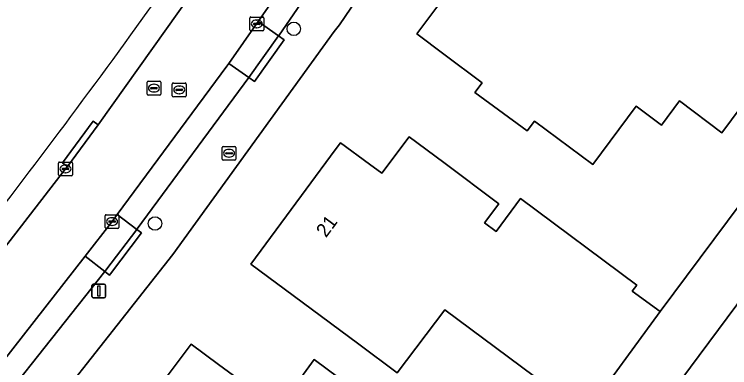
# Model space of a CAD drawing. Extents: x 158835 to 160077, y 386387 to 387778.
# Drawn here: x 159468.8 to 159520.8, y 386635.5 to 386661.1 of the extents above; entities that cross this region are included whole.
import ezdxf

# ---------------------------------------------------------------- set-up
doc = ezdxf.new("R2010")
doc.units = 0
for name, color, linetype in [('IMGEO_Boom', 7, 'Continuous'), ('IMGEO_Brandkraan', 7, 'Continuous'), ('IMGEO_Erf', 7, 'Continuous'), ('IMGEO_Grasland_agrarisch', 7, 'Continuous'), ('IMGEO_Groenvoorziening', 7, 'Continuous'), ('IMGEO_Kolk', 7, 'Continuous'), ('IMGEO_Lichtmast', 7, 'Continuous'), ('IMGEO_Pand', 7, 'Continuous'), ('IMGEO_Pand_nummerreeks', 7, 'Continuous'), ('IMGEO_Parkeervlak_open', 7, 'Continuous'), ('IMGEO_Rijbaan_lokaal_gesloten', 7, 'Continuous'), ('IMGEO_Rioolput', 7, 'Continuous'), ('IMGEO_Voetpad_open', 7, 'Continuous')]:
    doc.layers.add(name, color=color, linetype=linetype)

msp = doc.modelspace()

# ---------------------------------------------------------------- linework, layer by layer
at = {"layer": 'IMGEO_Boom'}
for centre in [(159489.093, 386660.084), (159479.003, 386645.952)]:
    msp.add_circle(centre, 0.489, dxfattribs=at)
at = {"layer": 'IMGEO_Brandkraan'}
for p, q in [((159483.884, 386650.623), (159483.884, 386651.475)), ((159483.959, 386651.549), (159484.811, 386651.549)), ((159484.372, 386651.329), (159484.397, 386651.329)), ((159484.885, 386651.475), (159484.885, 386650.623)), ((159484.143, 386651.043), (159484.143, 386651.055)), ((159484.581, 386651.006), (159484.183, 386651.006)), ((159484.186, 386651.092), (159484.584, 386651.092)), ((159484.395, 386650.769), (159484.37, 386650.769)), ((159484.627, 386651.055), (159484.627, 386651.043)), ((159484.811, 386650.549), (159483.959, 386650.549))]:
    msp.add_line(p, q, dxfattribs=at)
for points in [[(159483.884, 386650.623), (159483.884, 386651.475)], [(159483.959, 386651.549), (159484.811, 386651.549)], [(159484.885, 386651.475), (159484.885, 386650.623)], [(159484.811, 386650.549), (159483.959, 386650.549)]]:
    msp.add_lwpolyline(points, dxfattribs=at)
for centre, radius, start, end in [((159483.961, 386651.473), 0.0765, 91.552, 178.448), ((159483.961, 386651.473), 0.0765, 91.552, 178.448), ((159484.809, 386651.473), 0.0765, 1.552, 88.448), ((159484.809, 386651.473), 0.0765, 1.552, 88.448), ((159483.961, 386650.625), 0.0765, 181.552, 268.448), ((159483.961, 386650.625), 0.0765, 181.552, 268.448), ((159484.183, 386651.052), 0.0403, 85.8775, 175.7526), ((159484.18, 386651.042), 0.0366, 178.938, 274.7102), ((159484.584, 386651.049), 0.043, 264.8664, 352.4533), ((159484.588, 386651.054), 0.0386, 1.7309, 96.639), ((159484.809, 386650.625), 0.0765, 271.552, 358.448), ((159484.809, 386650.625), 0.0765, 271.552, 358.448)]:
    msp.add_arc(centre, radius, start, end, dxfattribs=at)
for centre, major_axis, ratio, start_param, end_param in [((159484.371, 386651.049), (-0.387, 0.002), 0.722429, 4.712389, 7.853982), ((159484.396, 386651.049), (-0.39, 0.002), 0.717154, 1.570796, 4.712389)]:
    msp.add_ellipse(centre, major_axis=major_axis, ratio=ratio, start_param=start_param, end_param=end_param, dxfattribs=at)
at = {"layer": 'IMGEO_Erf'}
for points in [[(159523.936, 386720.207), (159523.989, 386717.606), (159523.81, 386715.012), (159523.4, 386712.444), (159522.762, 386709.923), (159521.901, 386707.468), (159520.825, 386705.101), (159506.854, 386682.053), (159500.252, 386671.907), (159500, 386671.529), (159492.426, 386660.371), (159492.025, 386659.896), (159480.297, 386643.692), (159466.865, 386626.712)], [(159523.113, 386656.41), (159520.227, 386652.544), (159517.144, 386654.846), (159515.832, 386653.089), (159513.995, 386654.46), (159510.835, 386650.227), (159506.602, 386653.387), (159506.065, 386652.668), (159502.272, 386655.46), (159502.798, 386656.164), (159500, 386658.253), (159498.048, 386659.711), (159500, 386662.363)], [(159510.292, 386632.116), (159500.067, 386639.683), (159496.612, 386635.111), (159493.813, 386637.183), (159489.698, 386640.229), (159485.96, 386642.995), (159489.992, 386648.443), (159492.11, 386651.289), (159492.501, 386651.811), (159494.608, 386650.269), (159495.495, 386649.612), (159497.478, 386652.247), (159500, 386650.371), (159504.011, 386647.387), (159502.97, 386645.987), (159503.805, 386645.366), (159505.572, 386647.754), (159514.036, 386641.48), (159513.714, 386641.046), (159515.731, 386639.551), (159526.452, 386653.918)], [(159478.952, 386633.598), (159481.628, 386637.182), (159483.619, 386635.721), (159487.975, 386632.524), (159490.58, 386636.073), (159500, 386629.075)]]:
    msp.add_lwpolyline(points, dxfattribs=at)
for centre, radius, start, end in [((159034.245, 386981.09), 547.337, 323.34107, 325.81472), ((158997.141, 387009.134), 593.846, 321.080124, 323.307898)]:
    msp.add_arc(centre, radius, start, end, dxfattribs=at)
at = {"layer": 'IMGEO_Grasland_agrarisch'}
msp.add_lwpolyline([(159627.547, 386754.968), (159626.26, 386754.636), (159608.282, 386750), (159603.124, 386748.673), (159599.84, 386747.828), (159600.163, 386746.978), (159599.236, 386744.729), (159497.576, 386608.169), (159496.856, 386607.202), (159474.258, 386576.846)], dxfattribs=at)
at = {"layer": 'IMGEO_Groenvoorziening'}
msp.add_lwpolyline([(159599.236, 386744.729), (159600.163, 386746.978), (159599.84, 386747.828), (159595.413, 386746.689), (159591.302, 386741.165), (159576.147, 386720.781), (159563.63, 386703.915), (159558.058, 386696.441), (159540.934, 386673.397), (159533.385, 386663.269), (159529.001, 386657.369), (159526.452, 386653.918), (159515.731, 386639.551), (159510.292, 386632.116), (159505.124, 386625.269), (159502.142, 386621.255), (159495.593, 386611.141), (159497.576, 386608.169)], close=True, dxfattribs=at)
at = {"layer": 'IMGEO_Kolk'}
for p, q in [((159485.905, 386660.016), (159485.905, 386660.868)), ((159485.98, 386660.942), (159486.832, 386660.942)), ((159486.207, 386660.485), (159486.605, 386660.485)), ((159486.393, 386660.722), (159486.418, 386660.722)), ((159486.906, 386660.868), (159486.906, 386660.016)), ((159486.164, 386660.436), (159486.164, 386660.448)), ((159486.602, 386660.399), (159486.204, 386660.399)), ((159486.416, 386660.162), (159486.391, 386660.162)), ((159486.648, 386660.448), (159486.648, 386660.436)), ((159486.832, 386659.942), (159485.98, 386659.942)), ((159471.993, 386649.487), (159471.993, 386650.339)), ((159472.068, 386650.413), (159472.92, 386650.413)), ((159472.481, 386650.193), (159472.506, 386650.193)), ((159472.994, 386650.339), (159472.994, 386649.487)), ((159472.252, 386649.907), (159472.252, 386649.919)), ((159472.69, 386649.87), (159472.292, 386649.87)), ((159472.295, 386649.956), (159472.693, 386649.956)), ((159472.504, 386649.633), (159472.479, 386649.633)), ((159472.736, 386649.919), (159472.736, 386649.907)), ((159472.92, 386649.413), (159472.068, 386649.413)), ((159475.379, 386645.663), (159475.379, 386646.515)), ((159475.454, 386646.589), (159476.306, 386646.589)), ((159476.38, 386646.515), (159476.38, 386645.663)), ((159475.638, 386646.083), (159475.638, 386646.095)), ((159476.076, 386646.046), (159475.678, 386646.046)), ((159475.681, 386646.132), (159476.079, 386646.132)), ((159475.867, 386646.369), (159475.892, 386646.369)), ((159476.122, 386646.095), (159476.122, 386646.083)), ((159476.306, 386645.589), (159475.454, 386645.589)), ((159475.89, 386645.809), (159475.865, 386645.809))]:
    msp.add_line(p, q, dxfattribs=at)
for points in [[(159485.905, 386660.016), (159485.905, 386660.868)], [(159485.98, 386660.942), (159486.832, 386660.942)], [(159486.906, 386660.868), (159486.906, 386660.016)], [(159486.832, 386659.942), (159485.98, 386659.942)], [(159471.993, 386649.487), (159471.993, 386650.339)], [(159472.068, 386650.413), (159472.92, 386650.413)], [(159472.994, 386650.339), (159472.994, 386649.487)], [(159472.92, 386649.413), (159472.068, 386649.413)], [(159475.379, 386645.663), (159475.379, 386646.515)], [(159475.454, 386646.589), (159476.306, 386646.589)], [(159476.38, 386646.515), (159476.38, 386645.663)], [(159476.306, 386645.589), (159475.454, 386645.589)]]:
    msp.add_lwpolyline(points, dxfattribs=at)
for centre, radius, start, end in [((159485.982, 386660.866), 0.0765, 91.552, 178.448), ((159485.982, 386660.866), 0.0765, 91.552, 178.448), ((159486.204, 386660.445), 0.0403, 85.8775, 175.7526), ((159486.609, 386660.447), 0.0386, 1.7309, 96.639), ((159486.83, 386660.866), 0.0765, 1.552, 88.448), ((159486.83, 386660.866), 0.0765, 1.552, 88.448), ((159485.982, 386660.018), 0.0765, 181.552, 268.448), ((159485.982, 386660.018), 0.0765, 181.552, 268.448), ((159486.201, 386660.435), 0.0366, 178.938, 274.7102), ((159486.605, 386660.442), 0.043, 264.8664, 352.4533), ((159486.83, 386660.018), 0.0765, 271.552, 358.448), ((159486.83, 386660.018), 0.0765, 271.552, 358.448), ((159472.07, 386650.337), 0.0765, 91.552, 178.448), ((159472.07, 386650.337), 0.0765, 91.552, 178.448), ((159472.918, 386650.337), 0.0765, 1.552, 88.448), ((159472.918, 386650.337), 0.0765, 1.552, 88.448), ((159472.292, 386649.916), 0.0403, 85.8775, 175.7526), ((159472.289, 386649.906), 0.0366, 178.938, 274.7102), ((159472.693, 386649.913), 0.043, 264.8664, 352.4533), ((159472.697, 386649.918), 0.0386, 1.7309, 96.639), ((159472.07, 386649.489), 0.0765, 181.552, 268.448), ((159472.07, 386649.489), 0.0765, 181.552, 268.448), ((159472.918, 386649.489), 0.0765, 271.552, 358.448), ((159472.918, 386649.489), 0.0765, 271.552, 358.448), ((159475.456, 386646.513), 0.0765, 91.552, 178.448), ((159475.456, 386646.513), 0.0765, 91.552, 178.448), ((159476.304, 386646.513), 0.0765, 1.552, 88.448), ((159476.304, 386646.513), 0.0765, 1.552, 88.448), ((159475.678, 386646.092), 0.0403, 85.8775, 175.7526), ((159475.675, 386646.082), 0.0366, 178.938, 274.7102), ((159476.079, 386646.089), 0.043, 264.8664, 352.4533), ((159476.083, 386646.094), 0.0386, 1.7309, 96.639), ((159475.456, 386645.665), 0.0765, 181.552, 268.448), ((159475.456, 386645.665), 0.0765, 181.552, 268.448), ((159476.304, 386645.665), 0.0765, 271.552, 358.448), ((159476.304, 386645.665), 0.0765, 271.552, 358.448)]:
    msp.add_arc(centre, radius, start, end, dxfattribs=at)
for centre, major_axis, ratio, start_param, end_param in [((159486.392, 386660.442), (-0.387, 0.002), 0.722429, 4.712389, 7.853982), ((159486.417, 386660.442), (-0.39, 0.002), 0.717154, 1.570796, 4.712389), ((159472.48, 386649.913), (-0.387, 0.002), 0.722429, 4.712389, 7.853982), ((159472.505, 386649.913), (-0.39, 0.002), 0.717154, 1.570796, 4.712389), ((159475.866, 386646.089), (-0.387, 0.002), 0.722429, 4.712389, 7.853982), ((159475.891, 386646.089), (-0.39, 0.002), 0.717154, 1.570796, 4.712389)]:
    msp.add_ellipse(centre, major_axis=major_axis, ratio=ratio, start_param=start_param, end_param=end_param, dxfattribs=at)
at = {"layer": 'IMGEO_Lichtmast'}
for p, q in [((159474.417, 386640.653), (159474.417, 386641.453)), ((159474.417, 386641.453), (159474.417, 386640.653)), ((159474.517, 386641.553), (159475.307, 386641.553)), ((159475.307, 386641.553), (159474.517, 386641.553)), ((159475.407, 386641.453), (159475.407, 386640.653)), ((159475.407, 386640.653), (159475.407, 386641.453)), ((159475.307, 386640.553), (159474.517, 386640.553)), ((159474.517, 386640.553), (159475.307, 386640.553))]:
    msp.add_line(p, q, dxfattribs=at)
msp.add_lwpolyline([(159474.837, 386641.428), (159474.987, 386641.428), (159474.987, 386640.678), (159474.837, 386640.678), (159474.837, 386641.428)], dxfattribs=at)
for centre, start, end in [((159474.517, 386641.453), 90, 180), ((159474.517, 386641.453), 90, 180), ((159475.307, 386641.453), 0, 90), ((159475.307, 386641.453), 360, 90), ((159474.517, 386640.653), 180, 270), ((159474.517, 386640.653), 180, 270), ((159475.307, 386640.653), 270, 0), ((159475.307, 386640.653), 270, 0)]:
    msp.add_arc(centre, 0.1, start, end, dxfattribs=at)
at = {"layer": 'IMGEO_Pand'}
msp.add_lwpolyline([(159500, 386662.363), (159498.048, 386659.711), (159500, 386658.253), (159502.798, 386656.164), (159502.272, 386655.46), (159506.065, 386652.668), (159506.602, 386653.387), (159510.835, 386650.227), (159513.995, 386654.46), (159515.832, 386653.089), (159517.144, 386654.846), (159520.227, 386652.544), (159523.113, 386656.41)], dxfattribs=at)
for points in [[(159505.572, 386647.754), (159503.805, 386645.366), (159502.97, 386645.987), (159504.011, 386647.387), (159500, 386650.371), (159497.478, 386652.247), (159495.495, 386649.612), (159494.608, 386650.269), (159492.501, 386651.811), (159492.11, 386651.289), (159489.992, 386648.443), (159485.96, 386642.995), (159489.698, 386640.229), (159493.813, 386637.183), (159496.612, 386635.111), (159500.067, 386639.683), (159510.292, 386632.116), (159515.731, 386639.551), (159513.714, 386641.046), (159514.036, 386641.48)], [(159505.124, 386625.269), (159500, 386629.075), (159490.58, 386636.073), (159487.975, 386632.524), (159483.619, 386635.721), (159481.628, 386637.182), (159478.952, 386633.598), (159478.302, 386634.081), (159475.9, 386630.854), (159476.551, 386630.374), (159473.82, 386626.723), (159486.632, 386617.139), (159489.513, 386621.073), (159485.776, 386623.902), (159488.853, 386627.967), (159488.149, 386628.5), (159489.612, 386630.434), (159500, 386622.824), (159502.142, 386621.255)]]:
    msp.add_lwpolyline(points, close=True, dxfattribs=at)
at = {"layer": 'IMGEO_Parkeervlak_open'}
for points in [[(159497.546, 386673.509), (159495.988, 386674.563), (159488.253, 386663.123), (159486.494, 386660.609), (159487.977, 386659.57), (159488.022, 386659.633), (159494.875, 386669.563)], [(159485.827, 386656.543), (159484.364, 386657.566), (159484.227, 386657.37), (159476.255, 386646.598), (159477.681, 386645.519), (159477.708, 386645.554)], [(159475.346, 386642.471), (159473.919, 386643.589), (159465.699, 386633.096), (159462.673, 386629.428), (159464.074, 386628.284), (159464.152, 386628.38)]]:
    msp.add_lwpolyline(points, close=True, dxfattribs=at)
at = {"layer": 'IMGEO_Rijbaan_lokaal_gesloten'}
for points in [[(159513.878, 386721.278), (159513.869, 386716.038), (159513.796, 386715.241), (159513.584, 386713.955), (159513.258, 386712.692), (159512.821, 386711.465), (159512.275, 386710.281), (159511.626, 386709.15), (159501.61, 386692.371), (159500.806, 386691.095), (159500, 386689.822), (159499.36, 386688.811), (159497.335, 386685.65), (159492.103, 386677.614), (159491.469, 386676.644), (159491.393, 386676.531), (159488.703, 386672.537), (159488.647, 386672.459), (159474.87, 386653.114), (159472.629, 386650.095), (159472.496, 386649.912), (159463.597, 386638.445)], [(159465.699, 386633.096), (159473.919, 386643.589), (159475.879, 386646.09), (159476.255, 386646.598), (159484.227, 386657.37), (159484.364, 386657.566), (159486.494, 386660.609), (159488.253, 386663.123), (159495.988, 386674.563), (159498.178, 386677.802), (159500, 386680.496), (159500.64, 386681.505), (159502.694, 386684.743), (159505.787, 386689.619), (159516.302, 386707.245), (159517.076, 386708.722), (159517.443, 386709.606), (159517.715, 386710.261), (159518.213, 386711.852), (159518.439, 386712.887), (159518.568, 386713.481), (159518.776, 386715.135), (159518.834, 386716.37), (159518.864, 386721.239)]]:
    msp.add_lwpolyline(points, dxfattribs=at)
at = {"layer": 'IMGEO_Rioolput'}
for p, q in [((159478.424, 386655.351), (159478.424, 386656.203)), ((159478.499, 386656.277), (159479.351, 386656.277)), ((159478.683, 386655.771), (159478.683, 386655.783)), ((159478.726, 386655.82), (159479.124, 386655.82)), ((159478.912, 386656.057), (159478.937, 386656.057)), ((159479.167, 386655.783), (159479.167, 386655.771)), ((159479.425, 386656.203), (159479.425, 386655.351)), ((159480.262, 386655.224), (159480.262, 386656.076)), ((159480.337, 386656.15), (159481.189, 386656.15)), ((159480.75, 386655.93), (159480.775, 386655.93)), ((159481.263, 386656.076), (159481.263, 386655.224)), ((159479.351, 386655.277), (159478.499, 386655.277)), ((159479.121, 386655.734), (159478.723, 386655.734)), ((159478.935, 386655.497), (159478.91, 386655.497)), ((159480.521, 386655.644), (159480.521, 386655.656)), ((159480.959, 386655.607), (159480.561, 386655.607)), ((159480.564, 386655.693), (159480.962, 386655.693)), ((159480.773, 386655.37), (159480.748, 386655.37)), ((159481.005, 386655.656), (159481.005, 386655.644)), ((159481.189, 386655.15), (159480.337, 386655.15))]:
    msp.add_line(p, q, dxfattribs=at)
for points in [[(159478.424, 386655.351), (159478.424, 386656.203)], [(159478.499, 386656.277), (159479.351, 386656.277)], [(159479.425, 386656.203), (159479.425, 386655.351)], [(159480.262, 386655.224), (159480.262, 386656.076)], [(159480.337, 386656.15), (159481.189, 386656.15)], [(159481.263, 386656.076), (159481.263, 386655.224)], [(159479.351, 386655.277), (159478.499, 386655.277)], [(159481.189, 386655.15), (159480.337, 386655.15)]]:
    msp.add_lwpolyline(points, dxfattribs=at)
for centre, radius, start, end in [((159478.501, 386656.201), 0.0765, 91.552, 178.448), ((159478.501, 386656.201), 0.0765, 91.552, 178.448), ((159478.723, 386655.78), 0.0403, 85.8775, 175.7526), ((159479.128, 386655.782), 0.0386, 1.7309, 96.639), ((159479.349, 386656.201), 0.0765, 1.552, 88.448), ((159479.349, 386656.201), 0.0765, 1.552, 88.448), ((159480.339, 386656.074), 0.0765, 91.552, 178.448), ((159480.339, 386656.074), 0.0765, 91.552, 178.448), ((159481.187, 386656.074), 0.0765, 1.552, 88.448), ((159481.187, 386656.074), 0.0765, 1.552, 88.448), ((159478.501, 386655.353), 0.0765, 181.552, 268.448), ((159478.501, 386655.353), 0.0765, 181.552, 268.448), ((159478.72, 386655.77), 0.0366, 178.938, 274.7102), ((159479.124, 386655.777), 0.043, 264.8664, 352.4533), ((159479.349, 386655.353), 0.0765, 271.552, 358.448), ((159479.349, 386655.353), 0.0765, 271.552, 358.448), ((159480.561, 386655.653), 0.0403, 85.8775, 175.7526), ((159480.558, 386655.643), 0.0366, 178.938, 274.7102), ((159480.962, 386655.65), 0.043, 264.8664, 352.4533), ((159480.966, 386655.655), 0.0386, 1.7309, 96.639), ((159480.339, 386655.226), 0.0765, 181.552, 268.448), ((159480.339, 386655.226), 0.0765, 181.552, 268.448), ((159481.187, 386655.226), 0.0765, 271.552, 358.448), ((159481.187, 386655.226), 0.0765, 271.552, 358.448)]:
    msp.add_arc(centre, radius, start, end, dxfattribs=at)
for centre, major_axis, ratio, start_param, end_param in [((159478.911, 386655.777), (-0.387, 0.002), 0.722429, 4.712389, 7.853982), ((159478.936, 386655.777), (-0.39, 0.002), 0.717154, 1.570796, 4.712389), ((159480.749, 386655.65), (-0.387, 0.002), 0.722429, 4.712389, 7.853982), ((159480.774, 386655.65), (-0.39, 0.002), 0.717154, 1.570796, 4.712389)]:
    msp.add_ellipse(centre, major_axis=major_axis, ratio=ratio, start_param=start_param, end_param=end_param, dxfattribs=at)
at = {"layer": 'IMGEO_Voetpad_open'}
for points in [[(159452.919, 386610.024), (159466.865, 386626.712), (159480.297, 386643.692), (159492.025, 386659.896), (159492.426, 386660.371), (159500, 386671.529), (159500.252, 386671.907), (159506.854, 386682.053), (159520.825, 386705.101), (159521.901, 386707.468), (159522.762, 386709.923), (159523.4, 386712.444), (159523.81, 386715.012), (159523.989, 386717.606), (159523.936, 386720.207), (159523.829, 386721.437), (159523.607, 386726.844), (159524.846, 386728.532), (159523.605, 386733.299), (159523.378, 386733.241)], [(159434.001, 386603.754), (159434.251, 386604.023), (159438.438, 386608.651), (159445.723, 386616.887), (159445.368, 386617.173), (159447.821, 386620.028), (159448.174, 386619.761), (159449.947, 386621.841), (159460.729, 386634.881), (159460.383, 386635.173), (159462.739, 386638.108), (159463.101, 386637.845), (159463.597, 386638.445), (159472.496, 386649.912), (159472.629, 386650.095), (159472.275, 386650.344), (159474.5, 386653.37), (159474.87, 386653.114), (159488.647, 386672.459), (159487.016, 386673.557)], [(159494.875, 386669.563), (159488.022, 386659.633), (159487.977, 386659.57), (159488.386, 386659.284), (159486.234, 386656.254), (159485.827, 386656.543), (159477.708, 386645.554), (159477.681, 386645.519), (159478.024, 386645.26), (159475.777, 386642.302), (159475.697, 386642.196), (159475.346, 386642.471), (159464.152, 386628.38)]]:
    msp.add_lwpolyline(points, dxfattribs=at)
for points in [[(159487.977, 386659.57), (159486.494, 386660.609), (159484.364, 386657.566), (159485.827, 386656.543)], [(159488.386, 386659.284), (159487.977, 386659.57), (159485.827, 386656.543), (159486.234, 386656.254)], [(159472.629, 386650.095), (159474.87, 386653.114), (159474.5, 386653.37), (159472.275, 386650.344)], [(159477.681, 386645.519), (159476.255, 386646.598), (159475.879, 386646.09), (159473.919, 386643.589), (159475.346, 386642.471), (159475.42, 386642.565)], [(159478.024, 386645.26), (159477.681, 386645.519), (159475.42, 386642.565), (159475.346, 386642.471), (159475.697, 386642.196), (159475.777, 386642.302)]]:
    msp.add_lwpolyline(points, close=True, dxfattribs=at)
for centre, radius, start, end in [((159034.245, 386981.09), 547.337, 323.34107, 325.81472), ((158997.141, 387009.134), 593.846, 321.080124, 323.307898)]:
    msp.add_arc(centre, radius, start, end, dxfattribs=at)

# ---------------------------------------------------------------- texts
at = {"layer": 'IMGEO_Pand_nummerreeks'}
msp.add_text('21', height=1, rotation=53.4283, dxfattribs=at).set_placement((159491.439, 386644.875))

doc.saveas('drawing.dxf')
